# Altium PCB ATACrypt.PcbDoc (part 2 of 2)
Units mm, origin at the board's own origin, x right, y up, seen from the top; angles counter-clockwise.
Board outline 105.66 x 138.68 mm, 2 copper layers (Top Layer, Bottom Layer); 134 components, 213 nets, 662 pads, 171 vias.
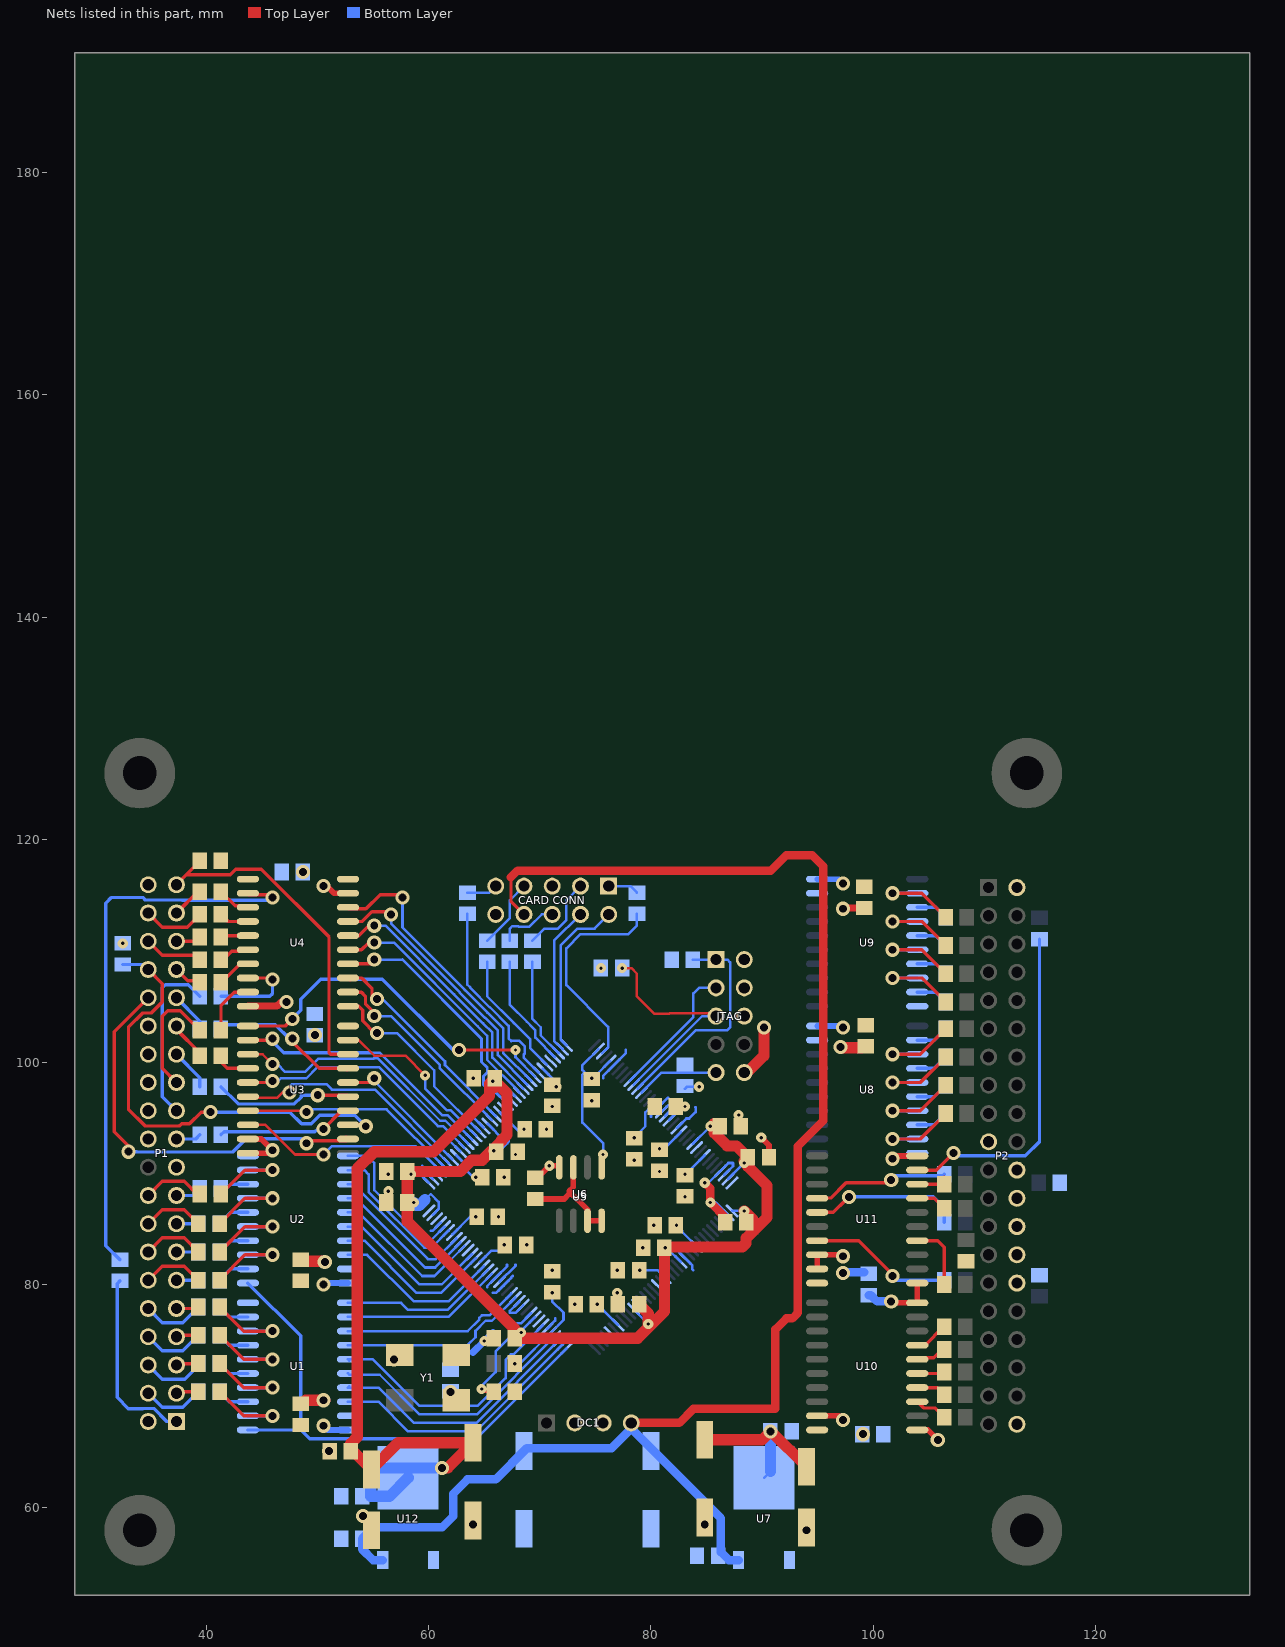
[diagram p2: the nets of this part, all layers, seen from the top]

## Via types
v1: diameter 1.27, hole 0.711, Top Layer to Bottom Layer, 100 vias
v2: diameter 0.914, hole 0.305, Top Layer to Bottom Layer, 71 vias

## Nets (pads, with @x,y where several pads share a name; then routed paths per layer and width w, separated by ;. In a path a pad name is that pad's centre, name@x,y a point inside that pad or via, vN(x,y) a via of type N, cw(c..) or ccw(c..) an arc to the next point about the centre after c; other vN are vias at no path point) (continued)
GND: "CARD CONN.10" C1.1 C2.1 C3.1 C4.1 C5.1 C6.1 C7.1 C8.1 C9.1 C10.1 C11.1 C12.1 C13.1 C14.1 C15.1 C16.1 C17.1 C18.1 C19.1 C20.1 C21.1 C22.1 C23.1 C24.1 C25.1 C26.1 C27.1 C28.1 C29.1 C30.1 C31.1 C33.1 C34.1 C35.1 C36.2 C37.2 C38.1 C39.1 C40.2 C41.2 C42.2 C43.2 DC1.2 DC1.3 JTAG.2 JTAG.10 P1.2 P1.19 P1.22 P1.24 P1.26 P1.28 P1.30 P1.40 P2.2 P2.19 P2.22 P2.24 P2.26 P2.28 P2.30 P2.40 R34.1 R35.1 R64.1 R66.1 R73.1 U1.10 U1.19 U2.10 U2.19 U3.9 U3.10 U4.10 U4.19 U5.6 U5.17 U5.18 U5.19 U5.22 U5.27 U5.33 U5.34 U5.36 U5.38 U5.39 U5.49 U5.56 U5.61 U5.68 U5.78 U5.80 U5.84 U5.85 U5.89 U5.90 U5.91 U5.98 U5.105 U5.106 U5.108 U5.110 U5.111 U5.117 U5.123 U5.128 U5.130 U5.140 U6.4 U7.1 U8.10 U8.19 U9.10 U9.19 U10.1 U10.10 U10.19 U11.1 U11.10 U11.18 U11.19 U12.1 Y1.2 | length 98.5
  Top Layer w0.508: U3.10@43.76,91.821 45.72,91.821 v1(45.974,92.075) 44.958,93.091 U3.9@43.76,93.091 ; v1(50.546,115.824) 50.871,115.824 51.506,115.189 U4.19@52.76,115.189 ; C6.1@56.2,87.376 56.2,87.696 56.388,87.884 v2(56.388,88.392) ; C29.1@69.596,89.596 69.784,89.596 v2@70.854,90.666 ; C29.1@69.784,89.962 C29.1@70.092,89.962 ; v2@70.782,90.475 70.854,90.475 v2@70.854,90.666 ; C14.1@70.902,96.078 C14.1@71.12,96.078 ; U6.4@71.755,90.538 71.615,90.678 v2(70.866,90.678) ; v2(76.962,79.248) 76.962,78.298 C23.1@77.028,78.232 ; C10.1@87.884,94.808 v2(87.884,95.25) ; v2(89.916,93.218) 90.612,92.522 C26.1@90.612,91.44 ; U10.19@94.941,68.199 96.901,68.199 v1(97.282,67.818) ; U11.19@94.941,81.407 U11.18@94.941,82.677 97.155,82.677 v1(97.282,82.55) ; v1(101.6,78.486) 101.727,78.359 U10.10@103.941,78.359 U11.1@103.941,80.137 ; v1(101.727,91.313) 101.981,91.567 U11.10@103.941,91.567 ; U10.1@103.941,66.929 104.902,66.929 v1(105.791,66.04) ; v2@70.854,90.666 70.854,90.678 v2(70.866,90.678) ; v2@70.854,90.666 v2(70.866,90.678)
  Top Layer w0.635: 45.085,105.029 U4.10@43.76,105.029 46.355,105.029 46.736,105.41 v1(47.244,105.41) ; v2(65.024,74.93) 65.598,74.93 C5.1@65.852,75.184 ; v1(97.282,113.792) 97.348,113.858 C31.1@99.187,113.858
  Top Layer w0.762: v2(84.836,89.154) 85.344,88.646 v2(85.344,87.376) 86.68,86.04 C25.1@86.68,85.598 ; JTAG.10@88.392,99.06 JTAG.10@88.646,99.06
  Top Layer w1.016: C4.1@48.768,69.403 48.961,69.596 v1(50.546,69.596) v1@50.673,69.596 ; C3.1@48.768,82.103 50.612,82.103 v1(50.673,82.042) ; JTAG.10@88.646,99.06 90.17,100.584 v1(90.17,103.124) ; v1(97.028,101.346) 97.089,101.285 C30.1@98.933,101.285
  Bottom Layer w0.229: 59.436,90.678 59.436,90.441 U5.110@60.384,89.493 ; 60.198,84.836 60.359,84.836 U5.105@61.091,85.568 ; 61.722,92.964 61.863,92.964 U5.117@62.859,91.968 ; 64.008,95.25 64.008,95.061 U5.123@64.98,94.089 ; 65.278,79.756 65.278,79.856 U5.91@66.041,80.618 67.056,81.634 67.056,81.788 ; 65.786,79.248 66.085,79.248 U5.89@66.748,79.911 67.426,80.589 67.426,80.634 67.564,80.772 ; U5.90@66.394,80.265 67.818,81.688 67.818,81.788 ; U5.85@68.162,78.497 67.31,77.645 67.31,77.47 67.572,77.47 67.584,77.483 67.855,77.483 U5.84@68.516,78.144 ; U5.78@70.637,76.022 71.374,76.759 71.374,76.962 ; 75.692,98.552 75.692,98.755 U5.6@76.683,99.746 77.724,100.787 77.724,101.092 ; 80.005,95.11 80.005,95.289 U5.17@80.572,95.857 81.489,96.774 81.534,96.774 ; U5.18@80.926,95.503 81.556,96.134 ; U5.19@81.279,95.15 82.042,95.912 82.042,96.266 ; U5.22@82.34,94.089 83.183,94.932 83.434,94.932 84.013,95.512 84.013,95.935 84.005,95.944 ; U5.49@83.047,82.386 82.296,83.137 82.296,83.162 83.724,81.734 83.724,81.376 83.82,81.28 ; v2(84.836,89.154) 85.183,89.154 U5.33@86.229,90.2 86.961,90.932 87.376,90.932 87.376,90.64 U5.34@86.582,89.846 ; U5.39@86.582,85.922 85.344,87.16 v2(85.344,87.376) 85.829,87.376 86.93,86.275 U5.38@86.936,86.275
  Bottom Layer w0.635: 64.008,73.914 v2(65.024,74.93) 65.786,75.692
  Bottom Layer w0.762: C28.1@99.568,79.06 99.756,79.06 100.33,78.486 v1(101.6,78.486)
  other v1: 93.98,57.912 64.008,58.42 84.836,58.42 54.102,59.182 51.054,65.024 56.896,73.279
  other v2: 73.152,78.232 71.12,81.28 76.962,81.28 79.248,83.312 68.834,83.566 80.264,85.344 66.294,86.106 83.058,87.884 66.802,89.662 56.388,89.916 80.772,90.17 78.486,91.186 67.818,91.694 70.612,93.98 71.12,96.012 74.676,96.52 64.008,98.552
H_CS0_N: P1.37 R27.2 | length 2.9
  Top Layer w0.305: P1.37@37.338,113.411 39.243,115.316 R27.2@39.436,115.316
H_CS1_N: P1.38 R28.2 | length 5.6
  Top Layer w0.305: P1.38@34.798,113.411 36.068,112.141 38.293,112.141 R28.2@39.436,113.284
H_DA0: P1.35 R29.2 | length 2.3
  Top Layer w0.305: P1.35@37.338,110.871 39.055,110.871 R29.2@39.436,111.252
H_DA1: P1.33 R31.2 | length 2.6
  Top Layer w0.305: P1.33@37.338,108.331 38.354,107.315 39.309,107.315 R31.2@39.436,107.188
H_DA2: P1.36 R30.2 | length 5.3
  Top Layer w0.305: P1.36@34.798,110.871 36.068,109.601 39.055,109.601 R30.2@39.436,109.22
H_DASP_N: P1.39 R67.1 U3.18 | length 31.1
  Top Layer w0.305: P1.39@37.338,115.951 38.227,116.84 ; R67.1@39.436,118.11 39.436,118.049 38.227,116.84 ; U3.18@52.76,100.711 51.181,100.711 51.054,100.838 51.054,111.252 44.958,117.348 42.672,117.348 42.164,116.84 38.227,116.84
  Bottom Layer w0.305: P1.39@37.338,115.951 P1.39@37.605,115.684
H_DD0: P1.17 R15.1 | length 2
  Bottom Layer w0.305: P1.17@37.338,88.011 R15.1@39.309,88.011
H_DD1: P1.15 R13.1 | length 2
  Bottom Layer w0.305: P1.15@37.338,85.471 R13.1@39.309,85.471
H_DD2: P1.13 R11.1 | length 2.2
  Top Layer w0.305: P1.13@37.338,82.931 P1.13@37.465,83.058
  Bottom Layer w0.305: P1.13@37.338,82.931 R11.1@39.309,82.931
H_DD3: P1.11 R9.1 | length 2
  Bottom Layer w0.305: P1.11@37.338,80.391 R9.1@39.309,80.391
H_DD4: P1.9 R7.1 | length 2
  Top Layer w0.305: P1.9@37.338,77.851 39.182,77.851 R7.1@39.309,77.724
H_DD5: P1.7 R5.1 | length 1.8
  Top Layer w0.305: P1.7@37.465,75.438 R5.1@39.309,75.438
H_DD6: P1.5 R3.1 | length 2.2
  Top Layer w0.305: P1.5@37.338,72.898 R3.1@39.309,72.898 R3.1@39.436,73.025
H_DD7: P1.3 R1.1 | length 2.3
  Top Layer w0.305: P1.3@37.338,70.358 39.055,70.358 39.182,70.231 R1.1@39.436,69.977
H_DD8: P1.4 R2.1 | length 5.6
  Bottom Layer w0.305: P1.4@34.798,70.231 36.068,68.961 37.912,68.961 R2.1@39.309,70.358
H_DD9: P1.6 R4.1 | length 5.9
  Bottom Layer w0.305: P1.6@34.798,72.771 36.068,71.501 38.1,71.501 39.403,72.804 39.436,72.837 39.436,72.898 R4.1@39.436,73.025
H_DD10: P1.8 R6.1 | length 5.6
  Bottom Layer w0.305: P1.8@34.798,75.311 36.068,74.041 37.912,74.041 R6.1@39.309,75.438
H_DD11: P1.10 R8.1 | length 5.6
  Bottom Layer w0.305: P1.10@34.798,77.851 36.068,76.581 37.912,76.581 R8.1@39.309,77.978
H_DD12: P1.12 R10.1 | length 5.6
  Top Layer w0.305: P1.12@34.798,80.391 36.068,81.661 38.039,81.661 R10.1@39.309,80.391
H_DD13: P1.14 R12.1 | length 5.6
  Top Layer w0.305: P1.14@34.798,82.931 36.068,84.201 38.039,84.201 R12.1@39.309,82.931
H_DD14: P1.16 R14.1 | length 5.6
  Top Layer w0.305: P1.16@34.798,85.471 36.068,86.741 38.039,86.741 R14.1@39.309,85.471
H_DD15: P1.18 R16.1 | length 5.6
  Top Layer w0.305: P1.18@34.798,88.011 36.068,89.281 38.039,89.281 R16.1@39.309,88.011
H_DIOR_N: P1.25 R18.1 | length 11.2
  Top Layer w0.305: P1.25@37.785,98.171 P1.25@37.338,98.171 36.068,99.441 36.068,104.14 36.55,104.622 37.684,104.622 R18.1@39.436,102.87
H_DIOW_N: P1.23 R19.1 | length 15.5
  Bottom Layer w0.305: P1.23@37.338,95.631 36.068,96.901 36.068,106.68 36.348,106.96 38.394,106.96 R19.1@39.436,105.918
H_DMACK_N: P1.29 R24.1 | length 3.3
  Top Layer w0.305: P1.29@37.338,103.251 37.338,102.936 R24.1@39.436,100.838
H_DMARQ: P1.21 R17.2 | length 2.4
  Top Layer w0.305: P1.21@37.338,93.091 P1.21@37.465,92.964
  Bottom Layer w0.305: P1.21@37.338,93.091 39.055,93.091 R17.2@39.436,93.472
H_INTRQ: P1.31 R26.2 | length 3.7
  Bottom Layer w0.305: P1.31@37.338,105.791 39.436,103.693 R26.2@39.436,102.997
H_IOCS16: P1.32 U3.12 | length 36.5
  Top Layer w0.305: v1@33.274,92.202 31.75,93.726 31.75,102.743 P1.32@34.798,105.791 ; v1(49.022,92.71) 49.251,92.939 52.608,92.939 U3.12@52.76,93.091 U3.12@52.607,93.244
  Bottom Layer w0.305: v1(33.02,91.948) 33.782,91.948 33.808,91.922 42.392,91.922 43.586,93.116 48.616,93.116 v1(49.022,92.71) ; P1.32@34.798,105.791 P1.32@35.052,105.791
H_IORDY: P1.27 R21.2 | length 3.8
  Bottom Layer w0.305: P1.27@37.338,100.711 39.436,98.613 R21.2@39.436,97.79
H_PDIAG_N: P1.34 R68.1 U3.13 | length 42.6
  Top Layer w0.305: P1.34@34.798,108.331 36.068,107.061 36.068,105.408 35.08,104.42 34.314,104.42 33.02,103.126 33.02,95.756 34.516,94.26 37.592,94.26 37.794,94.462 38.507,94.462 39.549,95.504 v1(40.386,95.504) ; U3.13@52.76,94.361 54.229,94.361 v1(54.356,94.234)
  Bottom Layer w0.305: R68.1@32.512,108.778 34.351,108.778 P1.34@34.798,108.331 ; v1(40.386,95.504) 47.537,95.504 48.578,94.463 49.453,94.463 50.215,95.225 53.365,95.225 v1(54.356,94.234)
H_RESET_N: P1.1 R23.2 | length 16.8
  Bottom Layer w0.305: R23.2@32.258,80.33 32.004,80.076 32.004,69.85 33.007,68.847 34.301,68.847 34.314,68.86 35.282,68.86 36.451,67.691 P1.1@37.338,67.691
HB_CS0_N: U4.17 U5.134 | length 24.7
  Top Layer w0.305: U4.17@52.76,112.649 54.026,112.649 54.915,113.538 56.388,113.538 v1(56.642,113.284)
  Bottom Layer w0.229: v1(56.642,113.284) 56.642,112.45 62.789,106.303 62.789,106.28 65.097,103.972 65.112,103.972 66.23,102.854 66.23,102.713 66.23,100.641 68.869,98.003 U5.134@68.869,97.978
HB_CS1_N: U4.16 U5.133 | length 23.9
  Top Layer w0.305: U4.16@52.76,111.379 53.721,111.379 54.61,112.268 v1(55.118,112.268) v1@55.118,111.858
  Bottom Layer w0.229: v1(55.118,112.268) 56.134,112.268 62.306,106.096 62.306,106.08 64.897,103.49 64.912,103.49 65.748,102.654 65.748,102.513 65.748,100.417 68.516,97.649 U5.133@68.516,97.624
HB_DA0: U4.15 U5.132 | length 22.5
  Top Layer w0.305: U4.15@52.76,110.109 53.975,110.109 54.61,110.744 v1(55.118,110.744)
  Bottom Layer w0.229: v1(55.118,110.744) 56.896,110.744 64.414,103.226 65.265,102.375 65.265,100.217 68.033,97.449 68.033,97.4 U5.132@68.162,97.271
HB_DA1: U4.13 U5.126 | length 19.6
  Top Layer w0.305: U4.13@52.887,107.696 U4.13@52.76,107.569 ; U4.13@52.912,107.417 U4.13@52.76,107.569 ; v1(55.372,105.664) 54.921,105.664 54.915,105.67 54.915,106.629 53.975,107.569 U4.13@52.76,107.569
  Bottom Layer w0.229: v1(55.372,105.664) 55.88,105.664 58.107,103.437 61.481,100.063 61.481,99.734 66.041,95.174 U5.126@66.041,95.15
HB_DA2: U4.14 U5.129 | length 22.5
  Top Layer w0.305: U4.14@52.76,108.839 54.737,108.839 v1(55.118,109.22)
  Bottom Layer w0.229: v1(55.118,109.22) 57.658,109.22
  Bottom Layer w0.254: 57.658,109.22 64.77,102.108 64.77,100.012 65.278,99.504 65.278,99.06 64.948,98.73 64.948,97.951 65.439,97.46 65.862,97.46 67.102,96.22 U5.129@67.102,96.21
HB_DASP_N: U3.2 U5.120 | length 23.9
  Top Layer w0.305: U3.2@43.76,101.981 45.847,101.981 v1(45.974,102.108)
  Bottom Layer w0.229: 54.844,100.838 55.626,100.838 61.252,95.212 61.736,95.212 U5.120@63.92,93.028
  Bottom Layer w0.305: v1@45.974,101.854 46.99,100.838 54.844,100.838
HB_DD0: U2.12 U5.103 | length 13.5
  Bottom Layer w0.229: U2.12@52.76,90.297 54.229,90.297 54.61,89.916 54.61,88.32 59.618,83.312 60.249,83.312 U5.103@61.798,84.861
HB_DD1: U2.14 U5.100 | length 13.6
  Bottom Layer w0.229: U2.14@52.76,87.757 53.467,87.757 59.69,81.534 60.593,81.534 U5.100@62.859,83.8
HB_DD2: U2.16 U5.97 | length 14.4
  Bottom Layer w0.229: U2.16@52.76,85.217 53.975,85.217 59.182,80.01 61.19,80.01 U5.97@63.92,82.74
HB_DD3: U2.18 U5.94 | length 15.3
  Bottom Layer w0.229: U2.18@52.76,82.677 54.483,82.677 58.674,78.486 61.787,78.486 U5.94@64.98,81.679
HB_DD4: U1.12 U5.92 | length 15.7
  Bottom Layer w0.229: U1.12@53.721,77.089 U1.12@52.76,77.089 61.804,77.089 61.972,77.256 ; 61.849,77.134 61.972,77.256 ; U5.92@65.687,80.972 61.972,77.256
HB_DD5: U1.14 U5.86 | length 17.2
  Bottom Layer w0.229: U1.14@52.76,74.549 63.507,74.549 64.224,75.266 64.224,75.836 65.134,76.746 65.704,76.746 U5.86@67.809,78.851
HB_DD6: U1.16 U5.76 | length 23
  Bottom Layer w0.229: U1.16@52.76,72.009 52.874,71.895 55.613,71.895 59.182,68.326 64.355,68.326 U5.76@71.344,75.315
HB_DD7: U1.18 U5.74 | length 23.6
  Bottom Layer w0.229: U1.18@52.76,69.469 55.499,69.469 58.166,66.802 64.245,66.802 U5.74@72.051,74.608
HB_DD8: U1.17 U5.75 | length 23.5
  Bottom Layer w0.229: U1.17@52.887,70.866 U1.17@52.76,70.739 55.499,70.739 58.674,67.564 64.3,67.564 U5.75@71.698,74.962
HB_DD9: U1.15 U5.79 | length 23.4
  Bottom Layer w0.229: U1.15@52.887,73.152 U1.15@52.76,73.279 54.991,73.279 59.182,69.088 64.413,69.088 66.927,71.601 66.927,73.24 67.41,73.724 67.627,73.724 70.28,76.376 U5.79@70.284,76.376
HB_DD10: U1.13 U5.87 | length 16.2
  Bottom Layer w0.229: U1.13@52.76,75.819 63.524,75.819 64.579,76.874 64.579,77.018 64.79,77.229 65.48,77.229 U5.87@67.455,79.204
HB_DD11: U1.11 U5.93 | length 14.3
  Bottom Layer w0.229: U1.11@52.76,78.359 57.531,78.359 58.166,77.724 61.722,77.724 65.324,81.326 U5.93@65.334,81.326
HB_DD12: U2.17 U5.96 | length 14.8
  Bottom Layer w0.229: U2.17@52.76,83.947 54.229,83.947 58.928,79.248 61.135,79.248 U5.96@64.273,82.386
HB_DD13: U2.15 U5.99 | length 13.9
  Bottom Layer w0.229: U2.15@52.76,86.487 53.721,86.487 59.436,80.772 60.538,80.772 U5.99@63.212,83.447
HB_DD14: U2.13 U5.101 | length 13.3
  Bottom Layer w0.229: U2.13@52.76,89.027 53.213,89.027 59.944,82.296 60.647,82.296 U5.101@62.505,84.154
HB_DD15: U2.11 U5.104 | length 13.8
  Bottom Layer w0.229: U2.11@52.76,91.567 54.483,91.567 55.118,90.932 55.118,89.408 ; 55.118,89.26 55.118,89.408 ; U5.104@61.445,85.215 60.304,84.074 59.539,84.074 55.118,88.495 55.118,89.408
HB_DD_DIR: U1.1 U2.1 U5.73 | length 47.5
  Bottom Layer w0.229: 56.769,66.167 64.317,66.167 U5.73@72.405,74.255
  Bottom Layer w0.305: U1.1@43.76,66.929 48.514,66.929 ; U2.1@43.76,80.137 48.514,75.383 48.514,66.929 ; 56.744,66.142 49.301,66.142 48.514,66.929
HB_DIOR_N: U4.11 U5.122 | length 17.7
  Top Layer w0.305: U4.11@52.76,105.029 53.721,105.029 54.077,104.673 54.077,103.709 55.169,102.616 v1(55.372,102.616)
  Bottom Layer w0.229: v1@55.626,102.616 57.15,102.616 60.515,99.251 60.515,97.829 64.609,93.735 U5.122@64.627,93.735
HB_DIOW_N: U4.12 U5.125 | length 18.5
  Top Layer w0.305: U4.12@52.887,106.172 U4.12@52.76,106.299 53.975,106.299 54.331,105.943 54.331,105.233 v1@55.423,104.14
  Bottom Layer w0.229: v1@55.423,104.14 56.642,104.14 60.998,99.784 60.998,99.485 U5.125@65.687,94.796
  other v1: 55.118,104.14
HB_DMACK_N: U3.16 U5.115 | length 13
  Top Layer w0.229: U3.16@52.76,98.171 54.991,98.171 55.245,98.425 55.261,98.441 v1@55.261,98.539
  Bottom Layer w0.229: v1@55.261,98.539 55.196,98.474 55.073,98.351 55.073,98.339 U5.115@62.152,91.26
  other v1: 55.118,98.552
HB_DMARQ: U3.6 U5.114 | length 22
  Top Layer w0.229: U3.6@43.76,96.901 43.874,96.787 46.39,96.787 47.139,97.536 47.244,97.536 v1(47.498,97.282)
  Bottom Layer w0.229: v1(47.498,97.282) 47.498,97.79 47.739,98.031 50.813,98.031 51.308,97.536 55.118,97.536 ; 55.169,97.536 U5.114@61.798,90.907
HB_INTRQ: U3.3 U5.119 | length 24.2
  Top Layer w0.229: U3.3@43.76,100.711 45.085,100.711 v1(45.974,99.822)
  Bottom Layer w0.229: v1(45.974,99.822) 46.405,99.822 47.103,99.124 48.909,99.124 50.102,100.317 55.06,100.317 55.098,100.355 55.426,100.355 61.052,94.729 61.511,94.729 U5.119@63.566,92.675 ; v1@45.974,100.253 v1@45.974,100.33
HB_IOCS16: U3.8 U5.112 | length 19.7
  Top Layer w0.229: U3.8@43.76,94.361 45.339,94.361 48.006,91.694 v1(50.546,91.694)
  Bottom Layer w0.229: v1(50.546,91.694) 51.308,92.456 58.835,92.456 U5.112@61.091,90.2
HB_IORDY: U3.5 U5.118 | length 23
  Top Layer w0.229: U3.5@43.76,98.171 45.847,98.171 v1(45.974,98.298)
  Bottom Layer w0.229: v1(45.974,98.298) 46.482,98.298 46.736,98.552 49.019,98.552 50.023,99.555 55.544,99.555 60.852,94.247 61.287,94.247 U5.118@63.213,92.321
HB_OE_N: U3.19 U5.121 | length 15.8
  Top Layer w0.229: U3.19@52.76,101.981 53.721,101.981 55.118,100.584 57.912,100.584 v2(59.69,98.806)
  Bottom Layer w0.229: v2(59.69,98.806) 59.69,97.639 61.634,95.694 61.96,95.694 U5.121@64.273,93.382
HB_PDIAG_N: U3.7 U5.113 | length 20.2
  Top Layer w0.229: U3.7@43.874,95.745 U3.7@43.76,95.631 48.895,95.631 v1(49.022,95.504)
  Bottom Layer w0.229: v1(49.022,95.504) 49.009,95.517 49.009,95.606 49.162,95.758 56.24,95.758 U5.113@61.445,90.553
HB_RESET_N: U4.18 U5.135 | length 26.9
  Top Layer w0.305: U4.18@52.76,113.919 52.887,113.792 54.379,113.792 55.649,115.062 57.404,115.062 v1(57.658,114.808)
  Bottom Layer w0.229: v1(57.658,114.808) 57.658,112.117 63.271,106.503 63.271,106.48 65.297,104.455 65.312,104.455 66.713,103.054 66.713,102.913 66.713,100.841 U5.135@69.223,98.332
HB_TR: U3.1 U5.136 | length 32.2
  Top Layer w0.305: U3.1@43.76,103.251 47.117,103.251 v1(47.752,103.886) ; v1(62.738,101.092) v2(67.818,101.092)
  Bottom Layer w0.229: v2(67.818,101.092) 67.818,100.443 U5.136@69.576,98.685
  Bottom Layer w0.305: v1(47.752,103.886) 48.514,104.648 48.514,105.664 50.317,107.467 55.855,107.467 62.23,101.092 v1(62.738,101.092)
LED: "CARD CONN.4" U5.143 | length 13.4
  Bottom Layer w0.229: U5.143@72.051,101.181 U5.143@72.051,101.16 71.298,101.913 71.298,110.922 73.66,113.284
NCE: R35.2 U5.16 | length 3.7
  Bottom Layer w0.229: v2(78.486,93.218) 79.502,94.234 79.502,95.494 U5.16@80.218,96.21
NCONFIG: R32.1 U5.20 | length 2.3
  Bottom Layer w0.229: U5.20@81.633,94.796 82.595,95.758 ; 82.595,95.758 83.058,95.758 82.595,95.758
  other v2: 83.058,96.012
NCSO: U5.2 U6.1 | length 10.9
  Bottom Layer w0.229: U5.2@75.269,101.16 73.838,99.729 73.838,99.288 73.977,99.148 73.977,99.021 73.838,98.881 73.838,94.564 75.692,92.71 v2(75.692,91.694)
"NetCARD CONN_1": "CARD CONN.1" R69.1 | length 2.8
  Bottom Layer w0.229: 76.2,115.824 78.166,115.824 R69.1@78.74,115.25
"NetCARD CONN_3": "CARD CONN.3" R70.1 | length 7.4
  Bottom Layer w0.229: R70.1@69.342,110.932 70.424,112.014 71.628,112.014 72.39,112.776 72.39,114.554 73.66,115.824
"NetCARD CONN_6": "CARD CONN.6" R74.2 | length 5.5
  Bottom Layer w0.229: R74.2@67.31,110.932 67.31,112.014 67.526,112.23 68.034,112.23 68.112,112.153 69.048,112.153 70.179,113.284 71.12,113.284
"NetCARD CONN_7": "CARD CONN.7" R71.1 | length 6.3
  Bottom Layer w0.229: R71.1@65.278,110.932 65.287,110.932 67.31,112.955 67.31,114.554 68.58,115.824
"NetCARD CONN_9": "CARD CONN.9" R72.1 | length 2.8
  Bottom Layer w0.229: R72.1@63.5,115.25 65.466,115.25 66.04,115.824
NetR1_2: R1.2 U1.2 | length 7.9
  Top Layer w0.305: R1.2@41.209,70.358 43.368,68.199 v1(45.974,68.199)
  Bottom Layer w0.305: U1.2@43.76,68.199 v1(45.974,68.199)
NetR2_2: R2.2 U1.3 | length 2.9
  Bottom Layer w0.305: R2.2@41.209,70.358 42.098,69.469 U1.3@43.76,69.469
NetR3_2: R3.2 U1.4 | length 7.9
  Top Layer w0.305: R3.2@41.209,72.898 43.368,70.739 v1(45.974,70.739)
  Bottom Layer w0.305: U1.4@43.76,70.739 v1(45.974,70.739)
NetR4_2: R4.2 U1.5 | length 2.9
  Bottom Layer w0.305: R4.2@41.209,72.898 42.098,72.009 U1.5@43.76,72.009
NetR5_2: R5.2 U1.6 | length 7.9
  Top Layer w0.305: R5.2@41.209,75.438 43.368,73.279 v1(45.974,73.279)
  Bottom Layer w0.305: U1.6@43.76,73.279 v1(45.974,73.279)
NetR6_2: R6.2 U1.7 | length 2.9
  Bottom Layer w0.305: R6.2@41.209,75.438 42.098,74.549 U1.7@43.76,74.549
NetR7_2: R7.2 U1.8 | length 7.9
  Top Layer w0.305: R7.2@41.209,77.978 43.368,75.819 v1(45.974,75.819)
  Bottom Layer w0.305: U1.8@43.76,75.819 v1(45.974,75.819)
NetR8_2: R8.2 U1.9 | length 2.9
  Bottom Layer w0.305: R8.2@41.209,77.978 42.098,77.089 U1.9@43.76,77.089
NetR9_2: R9.2 U2.2 | length 3
  Bottom Layer w0.305: R9.2@41.209,80.391 42.225,81.407 U2.2@43.76,81.407
NetR10_2: R10.2 U2.3 | length 7.9
  Top Layer w0.305: R10.2@41.209,80.391 43.495,82.677 v1(45.974,82.677)
  Bottom Layer w0.305: U2.3@43.76,82.677 v1(45.974,82.677)
NetR11_2: R11.2 U2.4 | length 3
  Bottom Layer w0.305: R11.2@41.209,82.931 42.225,83.947 U2.4@43.76,83.947
NetR12_2: R12.2 U2.5 | length 7.9
  Top Layer w0.305: R12.2@41.209,82.931 43.495,85.217 v1(45.974,85.217)
  Bottom Layer w0.305: U2.5@43.76,85.217 v1(45.974,85.217)
NetR13_2: R13.2 U2.6 | length 3
  Bottom Layer w0.305: R13.2@41.209,85.471 42.225,86.487 U2.6@43.76,86.487
NetR14_2: R14.2 U2.7 | length 7.9
  Top Layer w0.305: R14.2@41.209,85.471 43.495,87.757 v1(45.974,87.757)
  Bottom Layer w0.305: U2.7@43.76,87.757 v1(45.974,87.757)
NetR15_2: R15.2 U2.8 | length 3
  Bottom Layer w0.305: R15.2@41.209,88.011 41.59,88.392 42.225,89.027 U2.8@43.76,89.027
NetR16_2: R16.2 U2.9 | length 7.9
  Top Layer w0.305: R16.2@41.209,88.011 R16.2@41.336,88.138 43.495,90.297 v1(45.974,90.297)
  Bottom Layer w0.305: U2.9@43.76,90.297 v1(45.974,90.297)
NetR17_1: R17.1 U3.14 | length 12.3
  Top Layer w0.305: v1(50.546,93.98) 52.172,95.606 52.735,95.606 U3.14@52.76,95.631
  Bottom Layer w0.305: R17.1@41.336,93.472 41.615,93.751 49.453,93.751 49.479,93.726 49.784,93.726 50.038,93.98 v1(50.546,93.98)
NetR18_2: R18.2 U4.9 | length 5.1
  Top Layer w0.305: R18.2@41.336,102.87 41.336,105.09 42.545,106.299 U4.9@43.76,106.299
NetR19_2: R19.2 U4.8 | length 8.3
  Top Layer w0.305: U4.8@43.76,107.569 45.847,107.569 v1(45.974,107.442)
  Bottom Layer w0.305: R19.2@41.336,105.918 45.72,105.918 45.974,106.172 v1(45.974,107.442)
NetR21_1: R21.1 U3.15 | length 12.9
  Top Layer w0.305: v1@49.784,97.282 v1(50.038,97.028) 52.633,97.028 U3.15@52.76,96.901
  Bottom Layer w0.305: R21.1@41.336,97.79 42.885,96.241 47.929,96.241 48.539,96.851 48.539,96.989 48.578,97.028 v1(50.038,97.028)
NetR23_1: R23.1 U4.2 | length 50.4
  Top Layer w0.305: U4.2@43.76,115.189 43.887,115.062 45.72,115.062 v1(45.974,114.808)
  Bottom Layer w0.305: R23.1@32.258,82.23 30.988,83.5 30.988,114.3 31.496,114.808 34.288,114.808 34.516,114.58 37.822,114.58 37.848,114.554 45.72,114.554 v1(45.974,114.808)
NetR24_2: R24.2 U3.4 | length 3.5
  Top Layer w0.305: R24.2@41.336,100.838 R24.2@41.336,100.584 41.336,100.015 41.91,99.441 U3.4@43.76,99.441
NetR26_1: R26.1 U3.17 | length 13.5
  Top Layer w0.305: v1(47.752,102.108) 47.752,101.854 50.165,99.441 U3.17@52.76,99.441 U3.17@52.633,99.314
  Bottom Layer w0.305: R26.1@41.336,102.997 41.717,103.378 46.228,103.378 47.498,102.108 v1(47.752,102.108)
NetR27_1: R27.1 U4.3 | length 3
  Top Layer w0.305: R27.1@41.336,115.316 42.606,114.046 43.633,114.046 U4.3@43.76,113.919
NetR28_1: R28.1 U4.4 | length 2.7
  Top Layer w0.305: R28.1@41.336,113.284 41.971,112.649 U4.4@43.76,112.649
NetR29_1: R29.1 U4.5 | length 2.5
  Top Layer w0.305: R29.1@41.336,111.252 41.463,111.379 U4.5@43.76,111.379
NetR30_1: R30.1 U4.6 | length 2.8
  Top Layer w0.305: R30.1@41.336,109.22 41.529,109.22 42.291,109.982 43.633,109.982 U4.6@43.76,110.109
NetR31_1: R31.1 U4.7 | length 2.4
  Top Layer w0.305: R31.1@41.336,107.188 41.402,107.188 U4.7@43.053,108.839
NetR36_2: R36.2 U8.2 | length 3
  Bottom Layer w0.305: U8.2@103.941,101.981 105.476,101.981 R36.2@106.492,102.997
NetR37_2: R37.2 U8.3 | length 7.9
  Top Layer w0.305: v1(101.727,100.711) 104.206,100.711 R37.2@106.492,102.997
  Bottom Layer w0.305: v1(101.727,100.711) U8.3@103.941,100.711
NetR38_2: R38.2 U8.4 | length 3
  Bottom Layer w0.305: U8.4@103.941,99.441 105.476,99.441 R38.2@106.492,100.457
NetR39_2: R39.2 U8.5 | length 7.9
  Top Layer w0.305: v1(101.727,98.171) 104.206,98.171 R39.2@106.492,100.457
  Bottom Layer w0.305: v1(101.727,98.171) U8.5@103.941,98.171
NetR40_2: R40.2 U8.6 | length 3
  Bottom Layer w0.305: U8.6@103.941,96.901 105.476,96.901 R40.2@106.492,97.917
NetR41_2: R41.2 U8.7 | length 7.9
  Top Layer w0.305: v1(101.727,95.631) 104.206,95.631 R41.2@106.492,97.917
  Bottom Layer w0.305: v1(101.727,95.631) U8.7@103.941,95.631
NetR42_2: R42.2 U8.8 | length 3
  Bottom Layer w0.305: U8.8@103.941,94.361 105.476,94.361 R42.2@106.492,95.377
NetR43_2: R43.2 U8.9 | length 7.9
  Top Layer w0.305: v1(101.727,93.091) 104.206,93.091 R43.2@106.492,95.377
  Bottom Layer w0.305: v1(101.727,93.091) U8.9@103.941,93.091
NetR44_2: R44.2 U9.2 | length 7.9
  Top Layer w0.305: v1(101.727,115.189) 104.333,115.189 R44.2@106.492,113.03
  Bottom Layer w0.305: v1(101.727,115.189) U9.2@103.941,115.189
NetR45_2: R45.2 U9.3 | length 2.9
  Bottom Layer w0.305: U9.3@103.941,113.919 105.603,113.919 R45.2@106.492,113.03
NetR46_2: R46.2 U9.4 | length 7.9
  Top Layer w0.305: v1(101.727,112.649) 104.333,112.649 R46.2@106.492,110.49
  Bottom Layer w0.305: v1(101.727,112.649) U9.4@103.941,112.649
NetR47_2: R47.2 U9.5 | length 2.9
  Bottom Layer w0.305: U9.5@103.941,111.379 105.603,111.379 R47.2@106.492,110.49
NetR48_2: R48.2 U9.6 | length 7.9
  Top Layer w0.305: v1(101.727,110.109) 104.333,110.109 R48.2@106.492,107.95
  Bottom Layer w0.305: v1(101.727,110.109) U9.6@103.941,110.109
NetR49_2: R49.2 U9.7 | length 2.9
  Bottom Layer w0.305: U9.7@103.941,108.839 105.603,108.839 R49.2@106.492,107.95
NetR50_2: R50.2 U9.8 | length 7.9
  Top Layer w0.305: v1(101.727,107.569) 104.333,107.569 R50.2@106.492,105.41
  Bottom Layer w0.305: v1(101.727,107.569) U9.8@103.941,107.569
NetR51_2: R51.2 U9.9 | length 2.9
  Bottom Layer w0.305: U9.9@103.941,106.299 105.603,106.299 R51.2@106.492,105.41
NetR52_1: R52.1 U10.3 | length 3
  Top Layer w0.305: U10.3@103.941,69.469 104.505,68.905 105.532,68.905 R52.1@106.365,68.072
NetR53_1: R53.1 U10.4 | length 2.7
  Top Layer w0.305: U10.4@103.941,70.739 105.73,70.739 R53.1@106.365,70.104
NetR54_1: R54.1 U10.5 | length 2.5
  Top Layer w0.305: U10.5@103.941,72.009 106.238,72.009 R54.1@106.365,72.136
NetR55_1: R55.1 U10.6 | length 2.8
  Top Layer w0.305: U10.6@103.941,73.279 104.068,73.406 105.41,73.406 106.172,74.168 R55.1@106.365,74.168
NetR56_1: R56.1 U10.7 | length 3.1
  Top Layer w0.305: U10.7@103.941,74.549 104.648,74.549 106.299,76.2 R56.1@106.365,76.2
NetR57_1: R57.1 U11.9 | length 30.5
  Top Layer w0.305: U11.9@103.941,90.297 105.664,90.297 v1(107.188,91.821)
  Bottom Layer w0.305: v1(107.188,91.821) 107.442,91.567 113.665,91.567 114.935,92.837 R57.1@114.935,111.064
NetR58_2: R58.2 U11.4 | length 6.2
  Top Layer w0.305: U11.4@103.941,83.947 105.791,83.947 106.365,83.373 R58.2@106.365,80.01 R58.2@106.365,79.883
NetR59_2: R59.2 U11.7 | length 2.8
  Top Layer w0.305: U11.7@103.941,87.757 105.476,87.757 R59.2@106.365,86.868
NetR60_2: R60.2 U11.8 | length 2.7
  Top Layer w0.305: U11.8@103.941,89.027 105.73,89.027 106.047,89.344 R60.2@106.365,89.662
NetR61_1: R61.1 U11.17 | length 13.2
  Top Layer w0.305: U11.17@95.068,84.074 U11.17@94.941,83.947 98.679,83.947 101.727,80.899 v1(101.727,80.772)
  Bottom Layer w0.305: v1(101.727,80.772) 102.108,80.391 R61.1@106.365,80.391
NetR62_1: R62.1 U11.15 | length 13.9
  Top Layer w0.305: U11.15@94.941,86.487 96.393,86.487 97.536,87.63 v1@97.536,87.884
  Bottom Layer w0.305: v1@97.536,87.884 97.561,87.909 97.79,87.909 105.385,87.909 106.365,86.929 R62.1@106.365,85.598
  other v1: 97.79,87.884
NetR63_1: R63.1 U11.14 | length 12.5
  Top Layer w0.305: U11.14@94.941,87.757 94.966,87.782 96.164,87.782 97.536,89.154 101.6,89.154 101.727,89.281 v1@101.854,89.408
  Bottom Layer w0.305: v1@101.854,89.408 101.854,89.662 101.981,89.789 106.238,89.789 R63.1@106.365,89.916
  other v1: 101.6,89.408
NSTATUS: R25.1 U5.82 | length 10
  Top Layer w0.229: v2(64.77,70.612) 65.024,70.358 R25.1@65.852,70.358
  Bottom Layer w0.229: v2(64.77,70.612) 64.77,70.866 66.04,72.136 66.04,73.994 67.501,75.454 67.501,76.034 67.984,76.517 68.31,76.517 69.223,77.43 U5.82@69.223,77.437
SD_CD: R70.2 U5.142 | length 9.2
  Bottom Layer w0.229: R70.2@69.342,109.032 69.342,103.886 70.091,103.137 70.091,102.47 70.091,102.413 U5.142@71.698,100.806 U5.142@71.698,100.831
SD_CS: R69.2 U5.3 | length 19.5
  Bottom Layer w0.229: U5.3@75.622,100.806 76.145,101.33 76.145,103.179 72.39,106.934 72.39,110.236 73.66,111.506 77.978,111.506 78.74,112.268 R69.2@78.74,113.35
SD_DI: R72.2 U5.137 | length 17.5
  Bottom Layer w0.229: R72.2@63.5,113.35 63.5,106.957 63.754,106.703 63.754,106.68 65.497,104.937 65.512,104.937 67.196,103.254 67.196,102.127 67.441,101.882 67.476,101.917 68.16,101.917 68.644,101.434 68.644,100.75 68.58,100.687 68.58,100.389 U5.137@69.93,99.039
SD_DO: R71.2 U5.139 | length 11.5
  Bottom Layer w0.229: R71.2@65.278,109.032 65.278,105.918 67.678,103.518 69.126,102.07 69.126,101.257 U5.139@70.637,99.746
SD_SCK: R74.1 U5.141 | length 10.3
  Bottom Layer w0.229: R74.1@67.31,109.032 67.31,105.156 68.834,103.632 69.342,103.124 69.609,102.857 69.609,102.213 71.344,100.477 U5.141@71.344,100.453
SW: "CARD CONN.2" U5.144 | length 14.7
  Bottom Layer w0.229: U5.144@72.405,101.513 71.882,102.036 71.882,110.49 73.406,112.014 74.93,112.014 76.2,113.284
TCK: JTAG.1 R34.2 U5.12 | length 19.9
  Bottom Layer w0.229: U5.12@78.804,97.624 84.05,102.87 86.868,102.87 87.122,103.124 87.122,108.966 86.868,109.22 JTAG.1@85.852,109.22 R34.2@83.754,109.22
TDI: JTAG.9 R20.1 U5.13 | length 7.4
  Bottom Layer w0.229: U5.13@79.158,97.271 80.947,99.06 83.058,99.06 JTAG.9@85.852,99.06
TDO: JTAG.3 U5.10 | length 12.5
  Bottom Layer w0.229: U5.10@78.097,98.332 83.82,104.054 83.82,106.172 84.328,106.68 JTAG.3@85.852,106.68
TMS: JTAG.5 R22.1 U5.11 | length 21.4
  Top Layer w0.229: v2(77.404,108.458) 78.232,108.458 78.74,107.95 78.74,105.918 80.328,104.331 81.622,104.331 81.685,104.394 85.598,104.394 JTAG.5@85.852,104.14
  Bottom Layer w0.229: U5.11@78.451,97.978 84.613,104.14 JTAG.5@85.852,104.14
VCC5: "CARD CONN.8" C34.2 C36.1 C37.1 C38.2 DC1.4 U7.3 U12.3 | length 147.1
  Top Layer w0.305: 67.465,116.685 67.411,116.632 67.411,114.453 68.58,113.284
  Top Layer w0.762: 67.411,116.632 68.001,117.222 90.788,117.222 92.184,118.618 94.488,118.618 95.504,117.602 95.504,94.742 93.218,92.456 93.218,77.47 92.71,76.962 92.184,76.962 91.186,75.964 91.186,68.834 83.82,68.834 82.55,67.564 DC1.4@78.232,67.564
  Bottom Layer w0.762: U12.3@55.881,55.228 55.008,55.228 54.036,56.2 C38.2@54.036,57.15 55.052,58.166 61.214,58.166 62.23,59.182 62.23,61.214 63.5,62.484 66.04,62.484 68.834,65.278 76.454,65.278 DC1.4@78.232,67.056 ; DC1.4@78.232,67.564 DC1.4@78.232,67.056 ; U7.3@87.885,55.228 87.012,55.228 86.294,55.946 86.294,58.994 80.01,65.278 DC1.4@78.232,67.056
VCC12: C5.2 C6.2 C7.2 C8.2 C9.2 C10.2 C23.2 C24.2 C25.2 C26.2 C39.2 C41.1 C43.1 R73.2 U5.26 U5.35 U5.37 U5.50 U5.62 U5.81 U5.107 U5.109 U5.124 U5.131 U12.4 | length 177.1
  Top Layer w1.016: v1(61.214,63.5) 61.722,63.5 C41.1@64.008,65.786 57.277,65.786 C43.1@54.864,63.373 53.02,65.217 53.02,65.72 53.594,66.294 53.594,90.424 55.118,91.948 60.452,91.948 65.486,96.982 65.486,98.064 C9.2@65.959,98.537 ; 65.974,97.724 C9.2@65.974,98.298 ; C9.2@65.974,98.044 C9.2@65.974,98.298 ; C9.2@65.974,98.244 C9.2@65.974,98.298 ; C23.2@78.928,78.232 79.756,77.404 v2(79.756,76.454) ; C10.2@85.664,94.488 85.664,94.234 85.664,93.66 86.868,92.456 87.696,92.456 C26.2@88.712,91.44 ; v2(88.392,86.614) 88.994,86.012 89.154,85.852 89.154,85.598 89.154,84.77 ; C26.2@88.392,91.12 C26.2@88.712,91.44 ; C9.2@65.959,98.537 65.959,98.298 67.056,97.201 67.056,93.476 66.594,93.014 66.594,92.944 64.824,91.174 63.87,91.174 62.866,90.17 C7.2@58.1,90.17 58.1,89.916 C6.2@58.1,87.376 58.1,85.664 67.752,76.012 C5.2@67.752,75.184 68.326,75.184 78.806,75.184 79.916,76.294 81.214,77.592 C24.2@81.214,83.312 81.287,83.385 88.211,83.385 88.539,83.713 88.539,84.155 89.154,84.77 ; C9.2@65.959,98.537 C9.2@65.974,98.552 C9.2@65.974,98.298 ; C26.2@88.712,91.44 88.712,90.932 88.712,90.612 90.424,88.9 90.424,86.04 89.281,84.897 89.154,84.77
  Bottom Layer w0.229: v2(58.42,89.916) 59.254,89.916 U5.109@60.031,89.139 ; 59.69,87.63 60.198,88.138 60.907,87.429 60.907,86.798 U5.107@60.384,86.275 ; U5.124@65.334,94.442 65.334,94.432 66.802,92.964 ; v2(65.786,98.298) 66.04,98.044 66.682,98.044 U5.131@67.809,96.917 ; v2(68.326,75.692) 68.326,75.833 U5.81@69.576,77.083 ; U5.62@78.451,77.79 78.451,77.765 79.756,76.46 v2(79.756,76.454) ; v2(81.28,83.312) 81.414,83.312 U5.50@82.693,82.033 ; U5.26@83.754,92.675 83.785,92.675 v2(85.344,94.234) ; U5.35@86.936,89.493 88.375,90.932 v2(88.392,90.932) ; U5.37@87.289,86.629 88.377,86.629 v2(88.392,86.614)
  Bottom Layer w1.016: U12.4@58.166,62.628 56.498,60.96 54.798,60.96 54.798,63.18 55.118,63.5 v1(61.214,63.5) ; v2(58.674,87.376) 58.928,87.122 59.182,87.122 59.69,87.63 ; v2(65.857,92.019) 66.802,92.964
VCC33: "CARD CONN.5" C1.2 C2.2 C3.2 C4.2 C11.2 C12.2 C13.2 C14.2 C15.2 C16.2 C17.2 C18.2 C19.2 C20.2 C21.2 C22.2 C27.2 C28.2 C29.2 C30.2 C31.2 C33.2 C35.2 C40.1 C42.1 JTAG.4 JTAG.6 R20.2 R22.2 R25.2 R32.2 R33.2 R65.2 R67.2 R68.2 U1.20 U2.20 U3.20 U4.1 U4.20 U5.5 U5.23 U5.29 U5.46 U5.54 U5.66 U5.77 U5.95 U5.102 U5.116 U5.127 U5.138 U6.3 U6.7 U6.8 U7.4 U8.20 U9.20 U10.20 U11.20 Y1.1 Y1.4 | length 78.6
  Top Layer w0.229: C11.2@64.188,85.598 64.479,85.889 64.512,85.922 C11.2@64.606,86.016 ; v2(64.262,89.662) 64.262,89.916 64.422,90.076 64.426,90.08 C12.2@64.606,90.08 ; C13.2@68.138,93.472 68.138,93.538 v2(68.58,93.98) ; C14.2@71.12,97.79 v2(71.492,97.79) C14.2@71.608,97.79
  Top Layer w0.508: C29.2@69.596,87.696 72.202,87.696 72.644,88.138 72.644,88.392 ; U6.3@73.025,90.538 73.025,88.773 72.644,88.392 ; U6.8@75.565,85.738 U6.7@74.295,85.738 74.295,86.741 72.644,88.392 ; C31.2@98.867,116.078 C31.2@99.187,115.758
  Top Layer w1.016: C40.1@84.836,66.04 89.982,66.04 v1(90.744,66.802) 90.805,66.802 C42.1@93.98,63.627
  Bottom Layer w0.229: U5.102@62.152,84.508 63.75,86.106 v2(64.262,86.106) ; U5.116@62.505,91.614 63.5,90.619 63.5,90.17 64.008,89.662 v2(64.262,89.662) ; U5.95@64.627,82.033 65.652,83.058 66.294,83.058 v2(66.802,83.566) ; U5.127@66.394,95.503 68.072,93.826 68.426,93.826 v2(68.58,93.98) ; v2(67.752,72.898) 68.22,72.898 U5.77@70.991,75.669 72.136,76.814 72.136,77.47 71.12,78.486 v2(71.12,79.248) ; U5.138@70.284,99.392 71.492,98.183 v2(71.492,97.79) 71.492,97.654 v2@71.374,97.536 ; v2(74.676,98.552) 74.93,98.806 75.036,98.806 U5.5@76.329,100.099 ; v2(75.184,78.232) 75.692,77.724 75.692,77.72 U5.66@77.036,76.376 ; v2(78.994,81.28) 80.618,81.28 U5.54@81.279,80.618 ; v2(80.772,92.202) 81.16,92.202 U5.23@82.693,93.735 ; v2(82.296,85.344) 82.804,84.836 82.804,84.75 U5.46@84.108,83.447 ; v2(83.058,89.916) 83.312,89.916 83.566,90.17 83.566,90.365 U5.29@84.815,91.614 ; R20.2@83.058,97.602 83.185,97.729 83.246,97.79 v2(84.328,97.79) ; U7.4@90.17,62.628 U7.4@90.744,63.202
  Bottom Layer w0.508: v1(50.546,67.31) 50.927,66.929 U1.20@52.76,66.929 ; v1@50.673,80.01 50.8,80.137 U2.20@52.76,80.137 ; U8.20@94.941,103.251 v1@96.901,103.251 ; U9.20@94.941,116.459 96.901,116.459 v1(97.282,116.078)
  Bottom Layer w0.762: v1(97.282,81.026) 97.282,81.078 97.296,81.092 C28.2@99.187,81.092
  Bottom Layer w1.016: U7.4@90.744,63.202 v1(90.744,66.802)
  other v1: 99.06,66.548 61.976,70.358 50.546,80.01 49.784,102.428 97.282,103.124 48.702,117.094
  other v2: 75.504,108.458 32.512,110.678
pads on no net: DC1.1 JTAG.7 JTAG.8 P1.20 P2.20 U3.11 U5.51 U5.52 U11.2

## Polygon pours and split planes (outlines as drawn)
VCC12 on Top Layer "Top Layer-No Net" (solid, remove dead copper, pour order 1001): 60.452,88.138 60.706,88.138 58.674,86.106 58.674,75.184 65.532,75.184 65.532,72.644 78.74,72.644 92.964,86.868 86.106,93.726 86.106,95.504 84.836,95.504 81.534,92.71 84.836,89.408 86.355,87.671 85.852,87.122 83.058,84.328 80.01,84.328 80.01,80.772 76.454,77.216 71.374,77.216
VCC12 on Top Layer "Top Layer-No Net" (solid, remove dead copper, pour order 1000): 52.832,98.387 67.818,98.298 66.649,96.851 66.649,89.614 64.778,89.614 61.271,85.996 61.271,65.252 60.804,64.77 52.854,64.77
VCC33 on Top Layer "Bottom Layer-No Net" (solid, remove dead copper, pour order 1002): 29.718,130.048 118.11,130.048 118.11,53.848 29.718,53.848
GND on Bottom Layer "Bottom Layer-No Net" (solid, remove dead copper, pour order 1005): 29.718,130.048 118.11,130.048 118.11,54.095 117.864,53.848 29.718,53.848

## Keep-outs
Keep-Out Layer:
  lines w0.229: 29.21,130.556 29.21,53.34 118.618,53.34 118.618,130.556
  lines w0.254: 29.21,130.602 118.618,130.602

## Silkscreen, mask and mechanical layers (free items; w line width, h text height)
Top Overlay:
  text "Data Security Solution" at 105.41,128.016 h3.05 r180
  text "*** HardCrypt ***" at 99.822,122.682 h3.05 r180
  text "(c) Krzysztof Jakubczyk" at 92.964,72.136 h1.52 r90
  text "HOST" at 38.862,57.658 h3.05
  text "HDD" at 100.33,57.658 h3.05
Bottom Overlay:
  text "PCB v1.1" at 105.918,120.65 h1.52 r180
